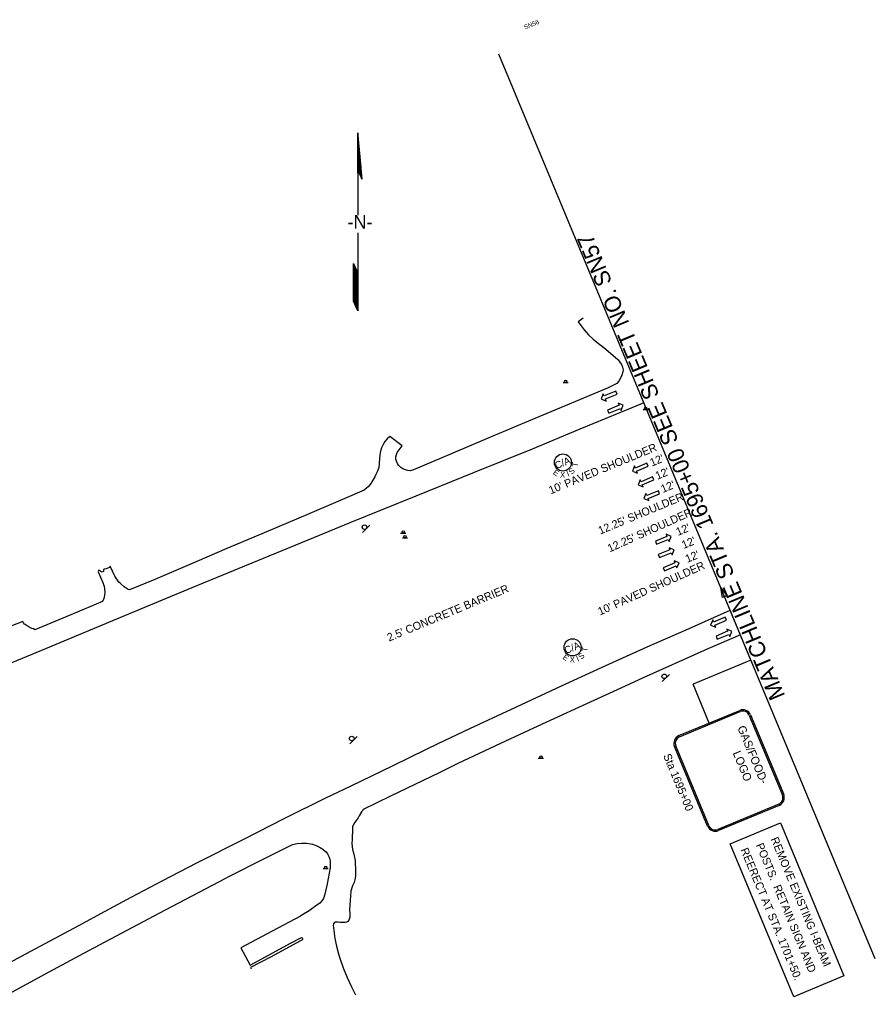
# Model space of a CAD drawing. Extents: x 1814695 to 1816409, y 1190422 to 1191819.
# Drawn here: x 1815661 to 1816409, y 1190956 to 1191819 of the extents above; entities that cross this region are included whole.
import ezdxf

# ---------------------------------------------------------------- set-up
doc = ezdxf.new("R2010")
doc.units = 0
for name, color, linetype in [('RD_EX_Road', 7, 'Continuous'), ('RD_PD_Final_LnLine', 7, 'Continuous'), ('RD_PD_Final_TX', 7, 'Continuous'), ('RD_SHT_MatchLine', 7, 'Continuous'), ('RD_SHT_TX', 7, 'Continuous'), ('RD_Sketch1', 7, 'Continuous'), ('RD_Sketch8', 7, 'Continuous'), ('SN_P_Signs', 7, 'Continuous')]:
    doc.layers.add(name, color=color, linetype=linetype)

# ---------------------------------------------------------------- blocks, each defined once
blk = doc.blocks.new('SARRW2')
at = {"layer": 'RD_PD_Final_LnLine'}
blk.add_lwpolyline([(-12, 1.2), (-12, -1.2), (-2.83, -1.2), (-2.83, -2.83), (0, 0), (-2.83, 2.83), (-2.83, 1.2)], close=True, dxfattribs=at)

msp = doc.modelspace()

# ---------------------------------------------------------------- linework, layer by layer
at = {"layer": 'RD_EX_Road'}
for points in [[(1816153.93, 1191558.34), (1816149.43, 1191555), (1816151.09, 1191552.66), (1816154.68, 1191548.12), (1816158.56, 1191543.83), (1816162.73, 1191539.81), (1816167.17, 1191536.09), (1816171.84, 1191532.68), (1816183.81, 1191522.32), (1816184.38, 1191521.77), (1816185.99, 1191519.85), (1816187.27, 1191517.7), (1816188.2, 1191515.38), (1816188.75, 1191512.94), (1816188.49, 1191511.33), (1816187.73, 1191508.51), (1816186.6, 1191505.81), (1816185.12, 1191503.29), (1816183.31, 1191501), (1816175.76, 1191497.39), (1816138.17, 1191481.55), (1816102.63, 1191466.69), (1816069.42, 1191452.75), (1816039.91, 1191440.26), (1816005.33, 1191425.68), (1816002.86, 1191424.66), (1816000.58, 1191424.86), (1815998.35, 1191425.44), (1815996.27, 1191426.39), (1815994.37, 1191427.69), (1815992.72, 1191429.29), (1815992.5, 1191429.55), (1815991.37, 1191431.19), (1815990.58, 1191433.02), (1815990.16, 1191434.97), (1815990.14, 1191436.97), (1815990.51, 1191438.93), (1815991.19, 1191440.66), (1815995.61, 1191446.62), (1815984.71, 1191454.75), (1815982.46, 1191452.63), (1815980.5, 1191450.24), (1815978.86, 1191447.62), (1815977.57, 1191444.81), (1815976.65, 1191441.86), (1815976.1, 1191438.82), (1815976.08, 1191438.58), (1815975.57, 1191431.98), (1815975.49, 1191429.91), (1815974.81, 1191426.77), (1815973.75, 1191423.73), (1815972.33, 1191420.85), (1815971.56, 1191419.59), (1815969.97, 1191416.46), (1815968.03, 1191413.52), (1815965.78, 1191410.82), (1815964.41, 1191409.45), (1815962.32, 1191407.67), (1815945.44, 1191400.5), (1815912.88, 1191386.61), (1815878.25, 1191371.9), (1815842.38, 1191356.72), (1815815.91, 1191345.33), (1815779.17, 1191329.62), (1815757.2, 1191320.56), (1815756.07, 1191320.95), (1815754.17, 1191321.94), (1815752.48, 1191323.26), (1815749.17, 1191326.02), (1815747.91, 1191327.32), (1815745.91, 1191329.82), (1815744.23, 1191332.54), (1815740.33, 1191341.34), (1815740.3, 1191341.39), (1815739.56, 1191340.23), (1815738.87, 1191339.68), (1815736.6, 1191338.91), (1815734.87, 1191338.8), (1815734.53, 1191338.5), (1815734.44, 1191336.69), (1815733.25, 1191335.94), (1815731.97, 1191336.58), (1815731.26, 1191337.39), (1815730.33, 1191337.71), (1815729.83, 1191336.43), (1815733.72, 1191327.03), (1815734.95, 1191323.6), (1815735.35, 1191321.75), (1815735.41, 1191321.27), (1815735.51, 1191318.47), (1815735.23, 1191315.67), (1815734.55, 1191312.94), (1815733.51, 1191310.34), (1815705.92, 1191298.77), (1815674.38, 1191285.7), (1815673.28, 1191286.31), (1815671.71, 1191286.81), (1815669.51, 1191287.85), (1815665.84, 1191290.18), (1815665.39, 1191290.56), (1815664.45, 1191291.74), (1815663.91, 1191292.94), (1815663.92, 1191292.94), (1815653.32, 1191288.85)], [(1816207.01, 1191484.27), (1816196.27, 1191479.86), (1816150.87, 1191461.2), (1816109.13, 1191443.79), (1816058.38, 1191423.34), (1816007.38, 1191402.49), (1815949.8, 1191379.1), (1815922.97, 1191368.16), (1815874.07, 1191348.04), (1815811.5, 1191322.3), (1815759.74, 1191300.64), (1815715.73, 1191282.34), (1815680.07, 1191267.47), (1815641.05, 1191251.54)], [(1815616.69, 1190975.15), (1815666.44, 1191002.14), (1815712.79, 1191027.01), (1815735.97, 1191039.5), (1815758.51, 1191051.55), (1815786.35, 1191066.25), (1815816.02, 1191081.58), (1815857.18, 1191102.55), (1815892.93, 1191120.69), (1815928.86, 1191138.48), (1815950.98, 1191149.21), (1815987.02, 1191166.58), (1816016.89, 1191181.08), (1816026.95, 1191186.16), (1816054.59, 1191199.21), (1816091.04, 1191216.15), (1816125.64, 1191232.31), (1816131.12, 1191234.86), (1816170.44, 1191252.94), (1816209.92, 1191270.66), (1816243.97, 1191285.71), (1816282.48, 1191302.66)], [(1816291.4, 1191281.2), (1816262.96, 1191269.05), (1816259.67, 1191267.63), (1816206.18, 1191243.48), (1816186.77, 1191234.6), (1816149.85, 1191217.69), (1816114.23, 1191201.34), (1816081.46, 1191186.01), (1816044.16, 1191168.54), (1816027.87, 1191160.58), (1815985.43, 1191139.93), (1815961.57, 1191128.34), (1815961.13, 1191127.39), (1815960.1, 1191126.32), (1815958, 1191122.88), (1815956.97, 1191121.17), (1815955.21, 1191118.76), (1815953.84, 1191116.78), (1815952.64, 1191114.57), (1815952.26, 1191113.11), (1815952.11, 1191111.8), (1815951.94, 1191102.17), (1815951.6, 1191098.73), (1815951.73, 1191095.92), (1815952.2, 1191093.38), (1815953.14, 1191090.36), (1815953.63, 1191087.78), (1815954.42, 1191083.81), (1815954.79, 1191073.79), (1815954.75, 1191069.96), (1815954.3, 1191066.88), (1815953.63, 1191064.41), (1815952.15, 1191061.55), (1815950.81, 1191057), (1815950.26, 1191052.89), (1815949.63, 1191040.61), (1815949.8, 1191037.35), (1815949.68, 1191034.08), (1815949.06, 1191031.39), (1815948.1, 1191030.3), (1815946.92, 1191029.81), (1815945.71, 1191029.54), (1815944.29, 1191029.58), (1815943.08, 1191029.54), (1815941.4, 1191029.52), (1815939.6, 1191029.73), (1815938.21, 1191029.85), (1815936.78, 1191029.65), (1815936.08, 1191029.15), (1815935.58, 1191028.45), (1815935.33, 1191027.1), (1815935.75, 1191022.42), (1815936.7, 1191015.53), (1815938.03, 1191008.7), (1815939.75, 1191001.96), (1815940.98, 1190998.21), (1815944.06, 1190989.7), (1815947.52, 1190981.33), (1815951.33, 1190973.13), (1815954.87, 1190966.3)], [(1815631.51, 1190956.2), (1815686.76, 1190986.28), (1815717.25, 1191002.64), (1815759.4, 1191025.21), (1815788.58, 1191040.67), (1815841.29, 1191068.26), (1815843.46, 1191069.38), (1815875.67, 1191085.82), (1815899.79, 1191097.8), (1815903.75, 1191098.53), (1815907.76, 1191098.87), (1815911.78, 1191098.81), (1815915.78, 1191098.36), (1815917.25, 1191098.1), (1815920.37, 1191097.01), (1815923.34, 1191095.55), (1815926.11, 1191093.75), (1815928.66, 1191091.64), (1815928.78, 1191091.52), (1815930.26, 1191089.54), (1815931.42, 1191087.34), (1815932.21, 1191084.99), (1815932.61, 1191082.54), (1815932.66, 1191081.63), (1815932.46, 1191077.26), (1815929.85, 1191063.23), (1815927.83, 1191054.23), (1815926.72, 1191050.56), (1815925.27, 1191048.39), (1815923.51, 1191046.46), (1815921.48, 1191044.82), (1815920.09, 1191043.96), (1815914.11, 1191039.73), (1815907.92, 1191035.82), (1815906.63, 1191035.07), (1815881.87, 1191021.8), (1815854.61, 1191007.41), (1815862.64, 1190992.1), (1815898.54, 1191011.68), (1815906.97, 1191016.14), (1815907.54, 1191016.28), (1815907.73, 1191016.25), (1815907.98, 1191015.96), (1815908.29, 1191015.41), (1815908.36, 1191014.5), (1815907.7, 1191013.9), (1815906.57, 1191013.31), (1815880.35, 1190999.03), (1815862.84, 1190990.2), (1815863.52, 1190988.92)]]:
    msp.add_lwpolyline(points, dxfattribs=at)
at = {"layer": 'RD_SHT_MatchLine'}
msp.add_line((1816409.26, 1190997.59), (1816080.21, 1191789.38), dxfattribs=at)
at = {"layer": 'RD_Sketch1'}
for p, q in [((1815956.91, 1191720.51), (1815956.7, 1191685.34)), ((1815960.64, 1191679.81), (1815956.91, 1191720.51)), ((1815956.91, 1191685.64), (1815956.91, 1191663.82)), ((1815957.21, 1191686.75), (1815960.64, 1191679.81)), ((1815956.91, 1191663.82), (1815956.91, 1191648.34)), ((1815956.91, 1191632.9), (1815956.91, 1191607.12)), ((1815952.92, 1191592.06), (1815952.92, 1191606.24)), ((1815952.92, 1191606.24), (1815956.91, 1191597.67)), ((1815956.91, 1191607.12), (1815956.91, 1191564.6)), ((1815952.92, 1191573.17), (1815952.92, 1191592.06)), ((1815956.91, 1191564.6), (1815952.92, 1191573.17))]:
    msp.add_line(p, q, dxfattribs=at)
for points in [[(1815956.92, 1191685.95), (1815956.92, 1191720.39)], [(1815957.02, 1191686.21), (1815957.02, 1191719.35)], [(1815957.11, 1191686.47), (1815957.11, 1191718.32)], [(1815957.21, 1191686.73), (1815957.21, 1191717.29)], [(1815957.3, 1191686.57), (1815957.3, 1191716.26)], [(1815957.39, 1191686.38), (1815957.39, 1191715.22)], [(1815957.49, 1191686.19), (1815957.49, 1191714.19)], [(1815957.58, 1191686), (1815957.58, 1191713.16)], [(1815957.68, 1191685.81), (1815957.68, 1191712.13)], [(1815957.77, 1191685.61), (1815957.77, 1191711.09)], [(1815957.87, 1191685.42), (1815957.87, 1191710.06)], [(1815957.96, 1191685.23), (1815957.96, 1191709.03)], [(1815958.06, 1191685.04), (1815958.06, 1191708)], [(1815956.83, 1191685.69), (1815956.83, 1191706.47)], [(1815958.15, 1191684.85), (1815958.15, 1191706.96)], [(1815958.25, 1191684.66), (1815958.25, 1191705.93)], [(1815958.34, 1191684.46), (1815958.34, 1191704.9)], [(1815958.43, 1191684.27), (1815958.43, 1191703.87)], [(1815958.53, 1191684.08), (1815958.53, 1191702.83)], [(1815958.62, 1191683.89), (1815958.62, 1191701.8)], [(1815958.72, 1191683.7), (1815958.72, 1191700.77)], [(1815958.81, 1191683.51), (1815958.81, 1191699.74)], [(1815958.91, 1191683.31), (1815958.91, 1191698.7)], [(1815956.73, 1191685.43), (1815956.73, 1191690.57)], [(1815959, 1191683.12), (1815959, 1191697.67)], [(1815959.1, 1191682.93), (1815959.1, 1191696.64)], [(1815959.19, 1191682.74), (1815959.19, 1191695.61)], [(1815959.28, 1191682.55), (1815959.28, 1191694.57)], [(1815959.38, 1191682.36), (1815959.38, 1191693.54)], [(1815959.47, 1191682.16), (1815959.47, 1191692.51)], [(1815959.57, 1191681.97), (1815959.57, 1191691.48)], [(1815959.66, 1191681.78), (1815959.66, 1191690.44)], [(1815959.76, 1191681.59), (1815959.76, 1191689.41)], [(1815959.85, 1191681.4), (1815959.85, 1191688.38)], [(1815959.95, 1191681.21), (1815959.95, 1191687.35)], [(1815960.04, 1191681.01), (1815960.04, 1191686.31)], [(1815960.14, 1191680.82), (1815960.14, 1191685.28)], [(1815960.23, 1191680.63), (1815960.23, 1191684.25)], [(1815960.32, 1191680.44), (1815960.32, 1191683.22)], [(1815960.42, 1191680.25), (1815960.42, 1191682.18)], [(1815960.51, 1191680.06), (1815960.51, 1191681.15)], [(1815960.61, 1191679.86), (1815960.61, 1191680.12)], [(1815953, 1191573), (1815953, 1191606.07)], [(1815953.09, 1191572.8), (1815953.09, 1191605.87)], [(1815953.18, 1191572.6), (1815953.18, 1191605.67)], [(1815953.28, 1191572.39), (1815953.28, 1191605.46)], [(1815953.37, 1191572.19), (1815953.37, 1191605.26)], [(1815953.47, 1191571.99), (1815953.47, 1191605.06)], [(1815953.56, 1191571.79), (1815953.56, 1191604.86)], [(1815953.66, 1191571.58), (1815953.66, 1191604.65)], [(1815953.75, 1191571.38), (1815953.75, 1191604.45)], [(1815953.85, 1191571.18), (1815953.85, 1191604.25)], [(1815953.94, 1191570.98), (1815953.94, 1191604.05)], [(1815954.03, 1191570.77), (1815954.03, 1191603.84)], [(1815954.13, 1191570.57), (1815954.13, 1191603.64)], [(1815954.22, 1191570.37), (1815954.22, 1191603.44)], [(1815954.32, 1191570.16), (1815954.32, 1191603.24)], [(1815954.41, 1191569.96), (1815954.41, 1191603.03)], [(1815954.51, 1191569.76), (1815954.51, 1191602.83)], [(1815954.6, 1191569.56), (1815954.6, 1191602.63)], [(1815954.7, 1191569.35), (1815954.7, 1191602.42)], [(1815954.79, 1191569.15), (1815954.79, 1191602.22)], [(1815954.88, 1191568.95), (1815954.88, 1191602.02)], [(1815954.98, 1191568.75), (1815954.98, 1191601.82)], [(1815955.07, 1191568.54), (1815955.07, 1191601.61)], [(1815955.17, 1191568.34), (1815955.17, 1191601.41)], [(1815955.26, 1191568.14), (1815955.26, 1191601.21)], [(1815955.36, 1191567.94), (1815955.36, 1191601.01)], [(1815955.45, 1191567.73), (1815955.45, 1191600.8)], [(1815955.55, 1191567.53), (1815955.55, 1191600.6)], [(1815955.64, 1191567.33), (1815955.64, 1191600.4)], [(1815955.74, 1191567.13), (1815955.74, 1191600.2)], [(1815955.83, 1191566.92), (1815955.83, 1191599.99)], [(1815955.92, 1191566.72), (1815955.92, 1191599.79)], [(1815956.02, 1191566.52), (1815956.02, 1191599.59)], [(1815956.11, 1191566.31), (1815956.11, 1191599.39)], [(1815956.21, 1191566.11), (1815956.21, 1191599.18)], [(1815956.3, 1191565.91), (1815956.3, 1191598.98)], [(1815956.4, 1191565.71), (1815956.4, 1191598.78)], [(1815956.49, 1191565.5), (1815956.49, 1191598.57)], [(1815956.59, 1191565.3), (1815956.59, 1191598.37)], [(1815956.68, 1191565.1), (1815956.68, 1191598.17)], [(1815956.77, 1191564.9), (1815956.77, 1191597.97)], [(1815956.87, 1191564.69), (1815956.87, 1191597.76)]]:
    msp.add_lwpolyline(points, dxfattribs=at)
at = {"layer": 'RD_Sketch8'}
for centre in [(1816136.14, 1191432), (1816144.59, 1191270.24)]:
    msp.add_circle(centre, 7.5, dxfattribs=at)
at = {"layer": 'SN_P_Signs'}
for p, q in [((1816136.23, 1191501.89), (1816140.73, 1191501.89)), ((1816206.17, 1191478.37), (1816210.67, 1191478.37)), ((1815960.89, 1191370.78), (1815967.25, 1191377.14)), ((1815994.21, 1191370.26), (1815998.71, 1191370.26)), ((1815995.86, 1191366.17), (1816000.36, 1191366.17)), ((1816300.59, 1191259.09), (1816274.32, 1191322.3)), ((1816300.59, 1191259.09), (1816250.03, 1191238.07)), ((1816222.98, 1191240.23), (1816229.34, 1191246.59)), ((1816264.16, 1191204.05), (1816250.03, 1191238.07)), ((1815949.73, 1191185.82), (1815956.09, 1191192.19)), ((1816114.61, 1191173.25), (1816119.11, 1191173.25)), ((1816282.29, 1191098.39), (1816326.26, 1191116.66)), ((1816326.26, 1191116.66), (1816381.92, 1190982.74)), ((1816337.95, 1190964.47), (1816282.29, 1191098.39)), ((1815926.46, 1191076.86), (1815930.96, 1191076.86)), ((1816381.92, 1190982.74), (1816337.95, 1190964.47))]:
    msp.add_line(p, q, dxfattribs=at)
msp.add_lwpolyline([(1816275.57, 1191313.94), (1816274.32, 1191322.3), (1816279.36, 1191315.52)], close=True, dxfattribs=at)
for points in [[(1816237.57, 1191193), (1816290.76, 1191215.1)], [(1816238.03, 1191191.89), (1816291.22, 1191213.99)], [(1816299.06, 1191210.76), (1816328.08, 1191140.94)], [(1816300.17, 1191211.22), (1816329.18, 1191141.4)], [(1816262.7, 1191113.77), (1816233.68, 1191183.59)], [(1816263.8, 1191114.23), (1816234.79, 1191184.05)], [(1816324.84, 1191133.1), (1816271.65, 1191111)], [(1816325.3, 1191131.99), (1816272.11, 1191109.89)]]:
    msp.add_lwpolyline(points, dxfattribs=at)
for centre, radius in [((1816138.49, 1191502.9), 1), ((1816208.43, 1191479.38), 1), ((1815962.65, 1191375.41), 2), ((1815996.47, 1191371.27), 1), ((1815998.12, 1191367.19), 1), ((1816224.74, 1191244.85), 2), ((1815951.49, 1191190.45), 2), ((1816116.87, 1191174.27), 1), ((1815928.72, 1191077.87), 1)]:
    msp.add_circle(centre, radius, dxfattribs=at)
for centre, radius, start, end in [((1816293.52, 1191208.45), 7.2, 22.56659, 112.56659), ((1816293.52, 1191208.45), 6, 22.56659, 112.56659), ((1816240.33, 1191186.35), 7.2, 112.56659, 202.56659), ((1816240.33, 1191186.35), 6, 112.56659, 202.56659), ((1816322.53, 1191138.64), 6, 292.56659, 22.56659), ((1816322.53, 1191138.64), 7.2, 292.56659, 22.56659), ((1816269.35, 1191116.54), 7.2, 202.56659, 292.56659), ((1816269.35, 1191116.54), 6, 202.56659, 292.56659)]:
    msp.add_arc(centre, radius, start, end, dxfattribs=at)

# ---------------------------------------------------------------- block references
at = {"layer": 'RD_PD_Final_LnLine', "xscale": 1.2000000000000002}
for p, yscale, rotation in [((1816169.6, 1191487.59), 1.2000000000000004, -157.44760385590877), ((1816188.94, 1191482.01), 1.2000000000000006, 22.552396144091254), ((1816196.86, 1191424.53), 1.2000000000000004, -157.44760385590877), ((1816201.86, 1191412.51), 1.2000000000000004, -157.44760385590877), ((1816206.85, 1191400.48), 1.2000000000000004, -157.44760385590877), ((1816230.81, 1191367.34), 1.2000000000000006, 22.552396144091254), ((1816233.39, 1191355.63), 1.2000000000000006, 22.552396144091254), ((1816237.72, 1191344.12), 1.2000000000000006, 22.552396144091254), ((1816265.29, 1191289.77), 1.2000000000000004, -157.44760385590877), ((1816283.88, 1191284.26), 1.2000000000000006, 22.552396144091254)]:
    msp.add_blockref('SARRW2', p, dxfattribs=dict(at, yscale=yscale, rotation=rotation))

# ---------------------------------------------------------------- texts
at = {"layer": 'RD_PD_Final_TX'}
for s, rotation, p in [("10' PAVED SHOULDER", 22.4268, (1816125.44, 1191404.07)), ("12'", 22.75903, (1816213.92, 1191428.32)), ("12'", 22.75903, (1816218.71, 1191416.78)), ("12'", 22.75903, (1816223.51, 1191405.24)), ("12.25' SHOULDER", 22.56659, (1816168.73, 1191368.85)), ("12.25' SHOULDER", 24.13303, (1816177.02, 1191353.28)), ("12'", 22.75903, (1816236.75, 1191367.7)), ("12'", 22.75903, (1816241.72, 1191356.24)), ("12'", 22.75903, (1816244.88, 1191344.07)), ("10' PAVED SHOULDER", 24.12164, (1816168.59, 1191298.07)), ("2.5' CONCRETE BARRIER", 22.57783, (1815984.11, 1191275.24))]:
    msp.add_text(s, height=7, rotation=rotation, dxfattribs=at).set_placement(p)
at = {"layer": 'RD_SHT_TX'}
for s, height, rotation, p in [('SN56', 4, 22.56659, (1816103.02, 1191810.74)), ('MATCHLINE STA. 1695+00 SEE SHEET NO. SN57', 14.1726, 112.67894, (1816330.71, 1191227.81))]:
    msp.add_text(s, height=height, rotation=rotation, dxfattribs=at).set_placement(p)
at = {"layer": 'RD_Sketch1'}
msp.add_text('-N-', height=11.811, rotation=0, dxfattribs=at).set_placement((1815947.72, 1191636.61))
at = {"layer": 'RD_Sketch8'}
for s, height, rotation, p in [('C/A', 6.25, 22.56659, (1816130.55, 1191426.12)), ('T', 5, 80.75173, (1816148.89, 1191427.87)), ('E', 5, 325.77783, (1816126.97, 1191422.21)), ('X', 5, 358.2072, (1816133.55, 1191418.82)), ('I', 5, 22.3672, (1816140.61, 1191419.51)), ('S', 5, 44.35903, (1816143.92, 1191421.07)), ('C/A', 6.25, 22.56659, (1816139, 1191264.37)), ('T', 5, 80.75173, (1816157.34, 1191266.11)), ('E', 5, 325.77783, (1816135.42, 1191260.46)), ('X', 5, 358.2072, (1816142, 1191257.07)), ('I', 5, 22.3672, (1816149.06, 1191257.76)), ('S', 5, 44.35903, (1816152.37, 1191259.32))]:
    msp.add_text(s, height=height, rotation=rotation, dxfattribs=at).set_placement(p)
at = {"layer": 'SN_P_Signs'}
for s, height, rotation, p in [('GAS/FOOD-', 7.2, 292.56659, (1816288.52, 1191199.97)), ('Sta 1695+00', 7, 292.56667, (1816223.65, 1191175.5)), ('LOGO', 7.2, 292.56659, (1816284.46, 1191177.86)), ('REMOVE EXISTING I-BEAM', 6.9998, 292.56667, (1816317.66, 1191102.53)), ('REERECT AT STA. 1701+50.', 6.9998, 292.56667, (1816291.25, 1191093.12)), ('POSTS.  RETAIN SIGN AND', 6.9998, 292.56667, (1816304.7, 1191097.26))]:
    msp.add_text(s, height=height, rotation=rotation, dxfattribs=at).set_placement(p)

doc.saveas('drawing.dxf')
